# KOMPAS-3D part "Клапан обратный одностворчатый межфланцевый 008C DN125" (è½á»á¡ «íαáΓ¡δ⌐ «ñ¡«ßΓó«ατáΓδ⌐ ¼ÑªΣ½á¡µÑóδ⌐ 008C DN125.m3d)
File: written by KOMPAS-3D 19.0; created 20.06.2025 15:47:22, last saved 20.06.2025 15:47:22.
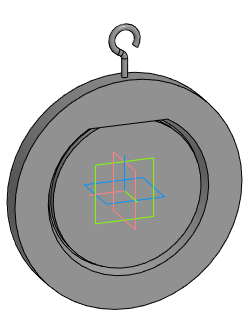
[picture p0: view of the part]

Document properties: Полное имя файла: E:\Dendor Работа Сачек\3D для проектировщиков\5.1 Тип 008C. Клапан обратный одностворчатый межфланцевый\stp_Клапан обратный одностворчатый межфланцевый 008C\Клапан обратный одностворчатый межфланцевый 008C DN125.m3d

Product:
- Part/product: Клапан обратный одностворчатый межфланцевый 008C DN125

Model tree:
1. Операция без истории:1  (labels: Клапан обратный одностворчатый межфланцевый 008C DN125)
